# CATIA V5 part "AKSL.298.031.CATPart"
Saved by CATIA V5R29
Part number: АКСЛ.298.031
Definition: Уголок 200 мм
Publications: "Грань по длине шипа", "Грань по ширине шипа"
Material "Steel": density 7860 kg/m3, Young's modulus 2e+11 Pa, Poisson ratio 0.266, thermal expansion 1.17e-05 1/K
Bounding box of the stored display mesh (mm): x -52 to 51, y -52 to 51, z -98 to 98
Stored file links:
  Z:\ООО Аксель\Соединения бруса\Соединения бруса\Соединения из листа\АКСЛ.298.030 (Трио)\AKSL.298.031.CATPart
  Z:\ООО Аксель\Соединения бруса\Соединения бруса\Соединения из листа\АКСЛ.298.030 (Трио)\AKSL.298.030.CATProduct
  Z:\ООО Аксель\Соединения бруса\Соединения бруса\Соединения из листа\АКСЛ.298.020 (Дуо)\AKSL.298.020.Skelet.CATPart
  Z:\#Catalog_GosNIIAS\Holes&Pockets\Part\Соединение шип-паз\Ship-Paz.CATPart
  Z:\ООО Аксель\Соединения бруса\Соединения бруса\Соединения из листа\АКСЛ.298.030 (Трио)\AKSL.298.034.CATPart
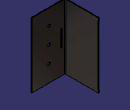
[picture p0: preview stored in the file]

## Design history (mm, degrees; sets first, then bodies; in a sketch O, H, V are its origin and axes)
External parameters (linked from other documents)
  `External.S металла` = 2 mm
  `External.R гиба` = 1.9 mm
  `External.K factor` = 0.49
SheetMetalParameters1: Thickness 2 {= `External.S металла`}, BendRadius 1.9 {= `External.R гиба`}, KFactor 0.49 {= `External.K factor`}, ReliefRadialLength 1, ReliefAxialLength 2, MinimumBendRadius 0
Set1 "Шип в центре грани"
  Extract1 "Плоскость шипа": ExtractElem face of Wall1
  Extract2 "Грань по длине шипа": ExtractElem edge of Extract1
  Extract3 "Грань по ширине шипа": ExtractElem edge of Extract1
Set2
  DatumSurface1: linked copy from another document
  DatumCurve1: linked copy from another document
  DatumCurve2: linked copy from another document
Body1 (main body)
  ThickSurface1: BotOffset 0, Surface DatumSurface1, TopOffset 2 {= `External.S металла`}
  Recognize1: Recognize_BendTable SheetMetalParameters1, Recognize_ReferenceFace face of ThickSurface1, Recognize_BendDefaultRadius 1.9 {= `External.R гиба`}, KFacteur 0.49 {= SheetMetalParameters1.KFactor}
  d_Bend1: Bend_BendTable SheetMetalParameters1, Bend_Thickness 2 {= `External.S металла`}, Bend_KFactor 0.49 {= SheetMetalParameters1.KFactor}, Bend_FirstSupport face of Recognize1, Bend_SecondSupport face of Recognize1, Bend_KFactorRadius 1.9 {= d_Bend1.CylindricalBendSurf_Radius}, Bend_Deduction -3.2761 {= (d_Bend1.CylindricalBendSurf_Radius+SheetMetalParameters1.Thickness*d_Bend1.Bend_KFactor)*(PI-abs(d_Bend1.BendSurf_OpenAngle))-2*(d_Bend1.CylindricalBendSurf_Radius+SheetMetalParameters1.Thickness)*tan(min((PI-abs(d_Bend1.BendSurf_OpenAngle)),(PI/2))/2)}
  Sketch1 on face of Recognize1, origin (-14.7796, -52, -71.2533), H (1, 0, 0), V (0, 0, 1)
    point P1 (13.7796, 23.2533)
    reference projected line E1 (64.7796, -26.7467) -> (-33.3204, -26.7467) from edge [face of Recognize1 | face of Recognize1]
    reference projected line E2 (-37.2204, 169.2533) -> (-37.2204, -26.7467) from edge [face of Recognize1 | face of d_Bend1]
    construction line L1 (64.7796, -26.7467) -> (64.7796, 36)
    distance E1 P1 = 50
    vertical: L1 V
    equidistance: E2 L1 P1
  Hole1: placed by Sketch1, at (-1, -52, -48) direction (0, 1, 0), diameter 8, through (limit type 6)
  RectPattern1: of Hole1, direction 1 instances 3, spacing 50, along edge [face of Recognize1 | face of Recognize1]
  CutOut1: Direction Sketch2, EndLimit through (limit type 2), Orientation true, Profile Sketch2, StartLimit through (limit type 2)
  Wall1: Thickness 2 {= `External.S металла`}, Profile Sketch3, ListTangentTo face of Recognize1, OffsetValue 0
  Sketch2 on DatumCurve1, origin (-40, -50, -23.9612), H (0, 0, 1), V (-1, 0, 0)
    reference projected line E1 (0, -3) -> (0, 0) from DatumCurve2
    reference projected line E2 (0, 0) -> (50, 0) from DatumCurve1
    construction line L1 (0, -1.5) -> (25, -1.5)
    point P5 (0, -1.5)
    point P6 (25, -1.5)
    axis line L2 (25, 0) -> (25, 7.3468)
    point P7 (25, 0)
    line L3 (50.1, -3.1) -> (50.1, 0.1)
    line L4 (50.1, 0.1) -> (-0.1, 0.1)
    line L5 (-0.1, 0.1) -> (-0.1, -3.1)
    line L6 (-0.1, -3.1) -> (50.1, -3.1)
    distance L5 E1 = 0.1
    distance E2 L4 = 0.1
    midpoint: P5 E1, P7 E2
    coincidence: L2 P6
    equidistance: L3 L5 P6, L4 L6 P6
    parallelism: L1 E2, L2 E1, L6 L4, L3 L5
  Sketch3 on face of Recognize1, origin (-52, -52, 0), H (1, 0, 0), V (0, 0, 1)
    reference projected line E1 (102, 98) -> (102, -98) from edge [face of Recognize1 | face of Recognize1]
    line L1 (103, -90) -> (102, -90)
    line L2 (102, -90) -> (102, 90)
    line L3 (102, 90) -> (103, 90)
    line L4 (103, 90) -> (103, -90)
    axis line L5 (102, 0) -> (103, 0)
    point P7 (102, 0)
    point P8 (103, 0)
    distance L2 L4 = 1 {= `External.S металла` /2}
    distance L1 L3 = 180
    length E1 = 196 (reference)
    perpendicularity: L2 L1
    midpoint: P7 L2, P8 L4, P7 E1
    coincidence: L2 E1
  Sketch4 on face of Recognize1, origin (-52, 0, 0), H (0, -1, 0), V (0, 0, 1)
    reference projected line E1 (-52, -98) -> (48.1, -98) from edge [face of Recognize1 | face of Recognize1]
    reference projected line E3 (-52, 98) -> (48.1, 98) from edge [face of Recognize1 | face of Recognize1]
    line L1 (-52, -98) -> (-51, -98)
    line L2 (-51, -98) -> (-51, -90.5)
    line L3 (-51, -90.5) -> (-50, -90.5)
    line L4 (-50, -90.5) -> (-50, 90.5)
    line L5 (-50, 90.5) -> (-51, 90.5)
    line L6 (-51, 90.5) -> (-51, 98)
    point P12 (-51, 98)
    line L7 (-51, 98) -> (-52, 98)
    line L8 (-52, 98) -> (-52, -98)
    distance L8 L4 = 2 {= `External.S металла`}
    distance L8 L2 = 1 {= `External.S металла` /2}
    distance L3 E1 = 7.5
    distance L6 L8 = 1 {= `External.S металла` /2}
    distance L5 E3 = 7.5
    horizontal: L1 H, L3 H, L5 H, L7 H
    vertical: L2 V, L6 V, L8 V, L4 V
    coincidence: P12 E3
  CutOut2: Direction Sketch4, EndLimit through (limit type 2), Orientation true, Profile Sketch4, StartLimit through (limit type 2), Thickness1 2, Thickness2 2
